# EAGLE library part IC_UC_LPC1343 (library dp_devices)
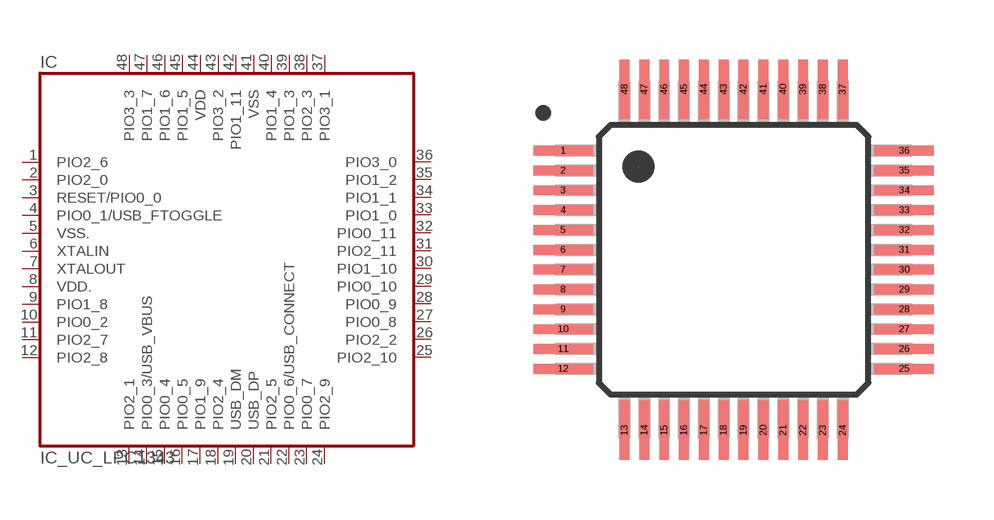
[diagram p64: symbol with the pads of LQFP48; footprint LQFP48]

Designator prefix IC

## IC_UC_LPC1343-LQFP48  [LQFP48]
1  PIO2_6
2  PIO2_0
3  RESET/PIO0_0
4  PIO0_1/USB_FTOGGLE
5  VSS.  pwr
6  XTALIN  in
7  XTALOUT  out
8  VDD.  pwr
9  PIO1_8
10  PIO0_2
11  PIO2_7
12  PIO2_8
13  PIO2_1
14  PIO0_3/USB_VBUS
15  PIO0_4
16  PIO0_5
17  PIO1_9
18  PIO2_4
19  USB_DM
20  USB_DP
21  PIO2_5
22  PIO0_6/USB_CONNECT
23  PIO0_7
24  PIO2_9
25  PIO2_10
26  PIO2_2
27  PIO0_8
28  PIO0_9
29  PIO0_10
30  PIO1_10
31  PIO2_11
32  PIO0_11
33  PIO1_0
34  PIO1_1
35  PIO1_2
36  PIO3_0
37  PIO3_1
38  PIO2_3
39  PIO1_3
40  PIO1_4
41  VSS  pwr
42  PIO1_11
43  PIO3_2
44  VDD  pwr
45  PIO1_5
46  PIO1_6
47  PIO1_7
48  PIO3_3

## Footprint LQFP48 (pad centres in mm)
smd 1.5 x 0.25: 1 -4.3,2.75; 2 -4.3,2.25; 3 -4.3,1.75; 4 -4.3,1.25; 5 -4.3,0.75; 6 -4.3,0.25; 7 -4.3,-0.25; 8 -4.3,-0.75; 9 -4.3,-1.25; 10 -4.3,-1.75; 11 -4.3,-2.25; 12 -4.3,-2.75; 25 4.3,-2.75; 26 4.3,-2.25; 27 4.3,-1.75; 28 4.3,-1.25; 29 4.3,-0.75; 30 4.3,-0.25; 31 4.3,0.25; 32 4.3,0.75; 33 4.3,1.25; 34 4.3,1.75; 35 4.3,2.25; 36 4.3,2.75
smd 0.25 x 1.5: 13 -2.75,-4.3; 14 -2.25,-4.3; 15 -1.75,-4.3; 16 -1.25,-4.3; 17 -0.75,-4.3; 18 -0.25,-4.3; 19 0.25,-4.3; 20 0.75,-4.3; 21 1.25,-4.3; 22 1.75,-4.3; 23 2.25,-4.3; 24 2.75,-4.3; 37 2.75,4.3; 38 2.25,4.3; 39 1.75,4.3; 40 1.25,4.3; 41 0.75,4.3; 42 0.25,4.3; 43 -0.25,4.3; 44 -0.75,4.3; 45 -1.25,4.3; 46 -1.75,4.3; 47 -2.25,4.3; 48 -2.75,4.3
